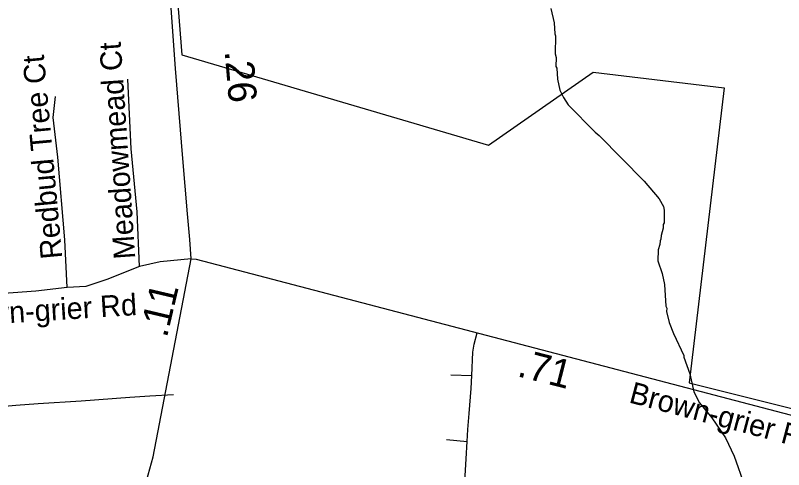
# Model space of a CAD drawing. Extents: x 1383679 to 1536984, y 460658 to 651027.
# Drawn here: x 1410412 to 1413802, y 516004 to 518010 of the extents above; entities that cross this region are included whole.
import ezdxf

# ---------------------------------------------------------------- set-up
doc = ezdxf.new("R2010")
doc.units = 0
for name, color, linetype in [('Default', 7, 'Continuous'), ('Exist Boundary Political City Limit New', 7, 'Continuous'), ('Exist Hydrographic Misc Water Feature', 7, 'Continuous'), ('Exist Road Non-System Type 51', 7, 'Continuous'), ('Exist Road Non-System Type 51 Label', 7, 'Continuous'), ('Exist Road Primary NC Attributed', 7, 'Continuous'), ('Exist Road Secondary Mileage Hundredths English Label', 7, 'Continuous'), ('Exist Road Secondary Type 51 Attributed', 7, 'Continuous'), ('Exist Road Secondary Type 51 Label', 7, 'Continuous'), ('Map Preparation Boundary City Limit Buffer Line', 7, 'Continuous')]:
    doc.layers.add(name, color=color, linetype=linetype)

msp = doc.modelspace()

# ---------------------------------------------------------------- linework, layer by layer
at = {"layer": 'Default'}
msp.add_lwpolyline([(1411077.1, 518711.9), (1411146.2, 517836.4), (1412499.6, 517437.2), (1412962, 517760), (1413538.8, 517689.9), (1413385.4, 516387.2), (1414314.9, 516154.5), (1414485.9, 516105.6), (1414805.9, 516048.2), (1414730, 516439.6), (1414754.4, 516537.3), (1415152.4, 517561.8), (1414825.6, 517681.2), (1414854.2, 517838.8), (1414774.9, 518103.9)], dxfattribs=at)
at = {"layer": 'Exist Boundary Political City Limit New'}
msp.add_lwpolyline([(1411077.1, 518711.9), (1411146.2, 517836.4), (1412499.6, 517437.2), (1412962, 517760), (1413538.8, 517689.9), (1413385.4, 516387.2), (1414314.9, 516154.5), (1414485.9, 516105.6), (1414805.9, 516048.2), (1414730, 516439.6), (1414754.4, 516537.3), (1415152.4, 517561.8), (1414825.6, 517681.2), (1414854.2, 517838.8), (1414774.9, 518103.9)], dxfattribs=at)
at = {"layer": 'Exist Hydrographic Misc Water Feature'}
msp.add_lwpolyline([(1412774.7, 518040.9), (1412789.3, 517976.6), (1412792.2, 517928.5), (1412796, 517920.4), (1412794.3, 517840.5), (1412798, 517824.4), (1412797.2, 517784.4), (1412801, 517776.4), (1412803.9, 517728.4), (1412814.9, 517680.1), (1412830.2, 517647.8), (1412851.5, 517615.3), (1412970.8, 517494.7), (1412988.6, 517480.3), (1413186.3, 517278), (1413252.6, 517200.5), (1413271.8, 517166.1), (1413275.5, 517150), (1413274.2, 517094), (1413270.1, 517086.1), (1413269.7, 517070.2), (1413261, 517038.4), (1413260.7, 517022.4), (1413256.5, 517014.5), (1413256.2, 516998.5), (1413247.7, 516974.7), (1413246.6, 516926.8), (1413265.4, 516870.3), (1413276.4, 516822.1), (1413282.3, 516726), (1413286.1, 516718), (1413285.7, 516702), (1413296.7, 516653.7), (1413315.6, 516605.3), (1413361.6, 516508.4), (1413361.4, 516500.4), (1413387.8, 516427.8), (1413406.1, 516347.4), (1413431.1, 516298.9), (1413485.6, 516233.7), (1413545.7, 516144.4), (1413584, 516063.5), (1413628.8, 515934.4)], dxfattribs=at)
at = {"layer": 'Exist Road Non-System Type 51'}
for p, q in [((1412333.4, 516423.6), (1412425.9, 516419.6)), ((1412314.2, 516136.8), (1412405.9, 516128.7))]:
    msp.add_line(p, q, dxfattribs=at)
for points in [[(1410959.4, 516901), (1410949.2, 517142.8), (1410923.5, 517420.5), (1410908, 517729)], [(1410640.8, 516808.5), (1410630.6, 517019.3), (1410599.7, 517384.5), (1410579.2, 517559.3), (1410589.5, 517651.9)], [(1411187.7, 516935.7), (1411051.9, 516921.6), (1410959.4, 516901)], [(1410959.4, 516901), (1410815.6, 516844.5), (1410723.1, 516813.6), (1410640.8, 516808.5)], [(1410640.8, 516808.5), (1410502.1, 516793), (1410301.7, 516777.6)], [(1412425.9, 516419.6), (1412431, 516523.2), (1412437, 516558.5), (1412449.5, 516607.7)], [(1412405.9, 516128.7), (1412408.9, 516182), (1412414.9, 516252.5), (1412422.9, 516362.2), (1412425.9, 516419.6)], [(1411109.6, 516335), (1411005.2, 516329), (1410916.9, 516322.5), (1410703.4, 516307.2), (1410513.4, 516295.6), (1410414.5, 516287.3), (1410313.9, 516279), (1410142.2, 516264.8), (1410111.9, 516262.2), (1410086.2, 516259.1), (1410064.4, 516256.4), (1410044.3, 516253.3), (1410023.4, 516249.3), (1410003.8, 516245.8), (1409971.8, 516239.5), (1409941.4, 516234.1), (1409906.3, 516227.7), (1409864.8, 516219.2), (1409795.7, 516207.5), (1409724.1, 516197), (1409690, 516192.2), (1409657.6, 516187.5), (1409638.1, 516186.9)], [(1412386.6, 515843.8), (1412391.8, 515903.2), (1412400.8, 516052.2), (1412405.9, 516128.7)]]:
    msp.add_lwpolyline(points, dxfattribs=at)
at = {"layer": 'Exist Road Primary NC Attributed'}
for points in [[(1411187.7, 516935.7), (1411181.5, 517020), (1411171.4, 517134), (1411151.1, 517377.6), (1411119.5, 517776.1), (1411099.8, 518041.4), (1411078.9, 518285.8), (1411032.8, 518883.4), (1411009.6, 519157), (1410997, 519315), (1410994.2, 519373.9), (1410994, 519410.3), (1410995.3, 519440.1), (1410999.3, 519475.3), (1411008.4, 519513), (1411017.5, 519537.8), (1411046.4, 519588.2)], [(1409747.8, 512561.3), (1409998.3, 513064.3), (1410344, 513730.6), (1410401.4, 513852.3), (1410419.8, 513897), (1410433.9, 513934.6), (1410453.2, 513991), (1410480.8, 514080), (1410499.9, 514151.8), (1410522.5, 514245.8), (1410546.9, 514357), (1410572.1, 514479.6), (1410626.3, 514774.6), (1410655.6, 514914.6), (1410678.2, 515006.9), (1410700.4, 515086.8), (1410727.8, 515180.8), (1410837.6, 515438.7), (1410923.6, 515683.5), (1410983.1, 515928.4), (1411020.7, 516060.5), (1411187.7, 516935.7)]]:
    msp.add_lwpolyline(points, dxfattribs=at)
at = {"layer": 'Exist Road Secondary Type 51 Attributed'}
msp.add_lwpolyline([(1411187.7, 516935.7), (1411210.2, 516934.3), (1414470.7, 516077.9), (1414580.8, 516050.7), (1414669.3, 516034.2), (1414716.2, 516028.2), (1414784.6, 516023.8), (1414812.9, 516024.5), (1415716.7, 516161.2)], dxfattribs=at)
at = {"layer": 'Map Preparation Boundary City Limit Buffer Line'}
msp.add_lwpolyline([(1411077.1, 518711.9), (1411146.2, 517836.4), (1412499.6, 517437.2), (1412962, 517760), (1413538.8, 517689.9), (1413385.4, 516387.2), (1414314.9, 516154.5), (1414485.9, 516105.6), (1414805.9, 516048.2), (1414730, 516439.6), (1414754.4, 516537.3), (1415152.4, 517561.8), (1414825.6, 517681.2), (1414854.2, 517838.8), (1414774.9, 518103.9)], dxfattribs=at)
msp.add_lwpolyline([(1411077.1, 518711.9), (1411146.2, 517836.4), (1412499.6, 517437.2), (1412962, 517760), (1413538.8, 517689.9), (1413385.4, 516387.2), (1414314.9, 516154.5), (1414485.9, 516105.6), (1414805.9, 516048.2), (1414730, 516439.6), (1414754.4, 516537.3), (1415152.4, 517561.8), (1414825.6, 517681.2), (1414854.2, 517838.8), (1414774.9, 518103.9)], dxfattribs=at)

# ---------------------------------------------------------------- texts
at = {"layer": 'Exist Road Non-System Type 51 Label'}
for s, rotation, p in [('Meadowmead Ct', 93.8657, (1410941.8, 516936.5)), ('Redbud Tree Ct', 95.2046, (1410619.7, 516938.4)), ('Brown-grier Rd', 3.6204, (1410098.8, 516633.3))]:
    msp.add_text(s, height=95, rotation=rotation, dxfattribs=at).set_placement(p)
at = {"layer": 'Exist Road Secondary Mileage Hundredths English Label'}
for s, rotation, p in [('.26', 274.8473, (1411335.6, 517851.9)), ('.11', 76.7812, (1411080.5, 516583.1)), ('.71', 345.6824, (1412622.1, 516417.7))]:
    msp.add_text(s, height=125, rotation=rotation, dxfattribs=at).set_placement(p)
at = {"layer": 'Exist Road Secondary Type 51 Label'}
msp.add_text('Brown-grier Rd', height=95, rotation=345.2171, dxfattribs=at).set_placement((1413115.5, 516301.8))

doc.saveas('drawing.dxf')
